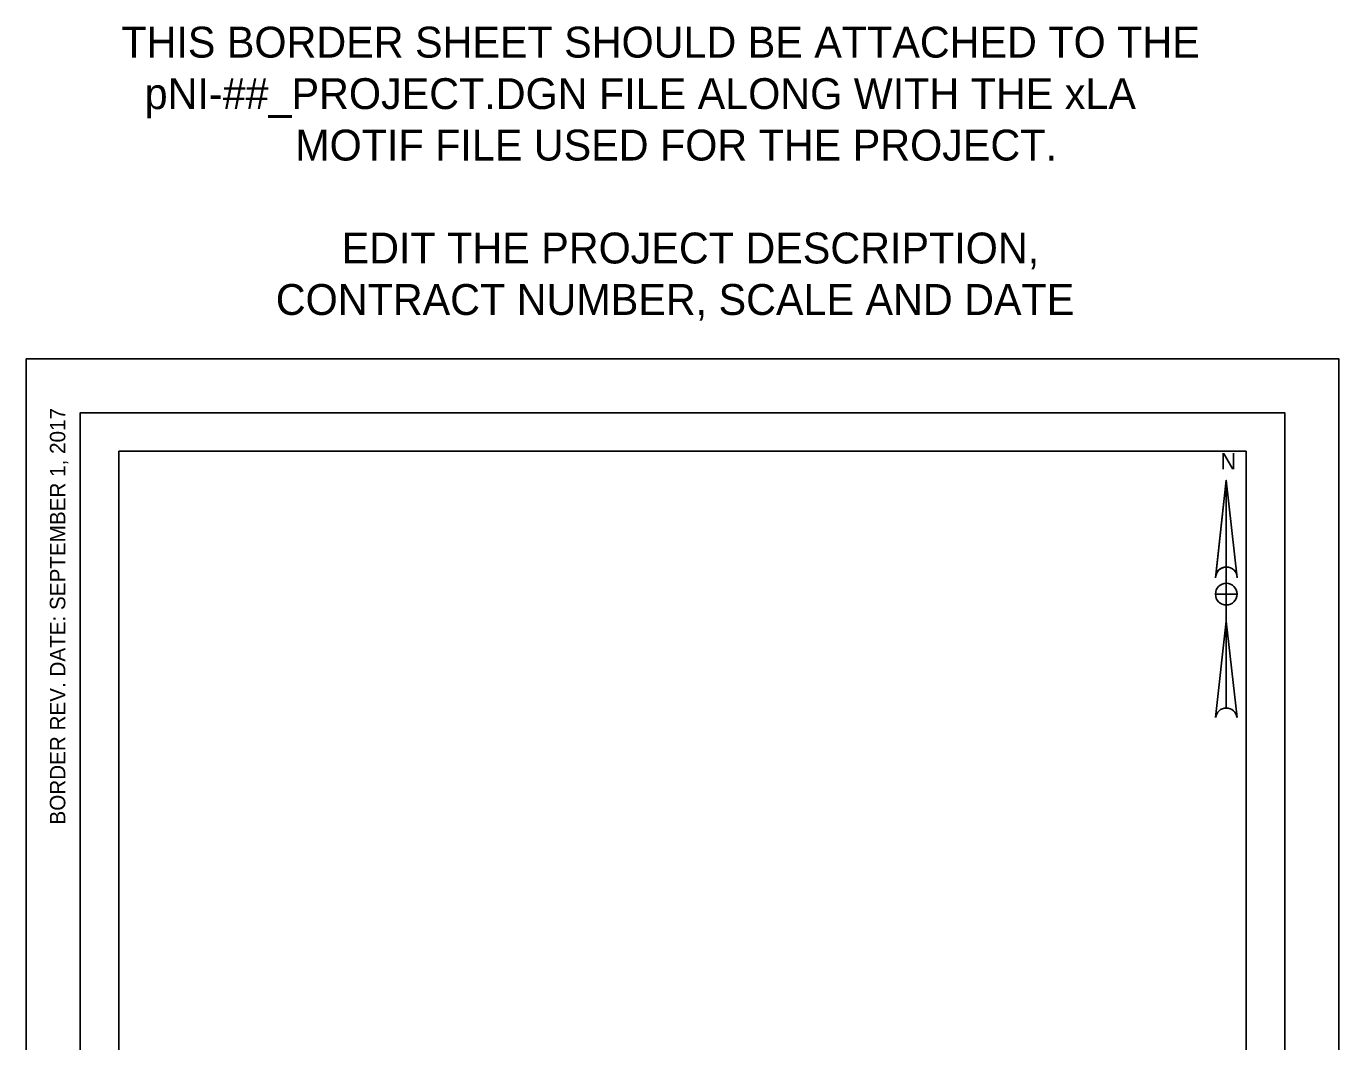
# Model space of a CAD drawing. Extents: x 0 to 8.5, y 0 to 13.2.
# Drawn here: x 0 to 8.5, y 6.58 to 13.15 of the extents above; entities that cross this region are included whole.
import ezdxf

# ---------------------------------------------------------------- set-up
doc = ezdxf.new("R2010")
doc.units = 0
for name, color, linetype in [('G-ANNO-SYMB', 7, 'Continuous'), ('G-BORD-LINE', 7, 'Continuous'), ('G-USER-CLIP', 7, 'Continuous'), ('G-USER-PAGE', 7, 'Continuous'), ('G-USER-TEXT', 7, 'Continuous')]:
    doc.layers.add(name, color=color, linetype=linetype)

msp = doc.modelspace()

# ---------------------------------------------------------------- linework, layer by layer
at = {"layer": 'G-ANNO-SYMB'}
for p, q in [((7.7016, 9.5803), (7.7718, 10.213)), ((7.7718, 8.7376), (7.7718, 10.213)), ((7.8421, 9.5803), (7.7718, 10.213)), ((7.7718, 9.4753), (7.7718, 9.5455)), ((7.7016, 9.4753), (7.7718, 9.4753)), ((7.7016, 9.4753), (7.7016, 9.4753)), ((7.7016, 9.4753), (7.7016, 9.4753)), ((7.8421, 9.4753), (7.7718, 9.4753)), ((7.7718, 9.4753), (7.7718, 9.405)), ((7.8421, 9.4753), (7.8421, 9.4753)), ((7.8421, 9.4753), (7.8421, 9.4753)), ((7.7025, 8.6755), (7.7718, 9.2993)), ((7.8412, 8.6755), (7.7718, 9.2993))]:
    msp.add_line(p, q, dxfattribs=at)
for points in [[(7.7718, 9.6505), (7.7718, 9.6505), (7.7718, 10.213), (7.7034, 9.5956)], [(7.7718, 9.5455), (7.7718, 9.4753), (7.8421, 9.4753)], [(7.7718, 9.405), (7.7718, 9.4753), (7.7016, 9.4753), (7.7016, 9.4753)], [(7.7718, 9.405), (7.7718, 9.405)], [(7.8412, 8.6755), (7.7718, 9.2993), (7.7718, 8.7376)]]:
    msp.add_lwpolyline(points, dxfattribs=at)
for centre, radius, start, end in [((7.772, 9.5802), 0.0703, 90, 180), ((7.772, 9.5802), 0.0703, 90.09047, 167.34843), ((7.772, 9.5802), 0.0703, 0, 90), ((7.7718, 9.4753), 0.0703, 90, 180), ((7.7718, 9.4753), 0.0703, 0, 90), ((7.7718, 9.4753), 0.0703, 0.00121, 89.99879), ((7.7718, 9.4753), 0.0703, 180, 270), ((7.7718, 9.4753), 0.0703, 180, 270), ((7.7718, 9.4753), 0.0703, 270, 360), ((7.7718, 8.6678), 0.0698, 6.34387, 173.65613), ((7.7718, 8.6678), 0.0698, 6.34387, 90)]:
    msp.add_arc(centre, radius, start, end, dxfattribs=at)
at = {"layer": 'G-BORD-LINE'}
msp.add_lwpolyline([(0.35, 0.8607), (0.35, 0.35), (8.15, 0.35), (8.15, 10.65), (0.35, 10.65), (0.35, 0.8607)], dxfattribs=at)
at = {"layer": 'G-USER-CLIP'}
msp.add_lwpolyline([(0.6, 10.4), (7.9, 10.4), (7.9, 2.35), (0.6, 2.35)], close=True, dxfattribs=at)
at = {"layer": 'G-USER-PAGE'}
msp.add_lwpolyline([(0, 11), (8.5, 11), (8.5, 0), (0, 0)], close=True, dxfattribs=at)

# ---------------------------------------------------------------- texts
at = {"layer": 'G-ANNO-SYMB'}
msp.add_text('N', height=0.105, dxfattribs=at).set_placement((7.7338, 10.2832))
at = {"layer": 'G-USER-TEXT'}
for s, p in [('THIS BORDER SHEET SHOULD BE ATTACHED TO THE', (0.6158, 12.9498)), ('pNI-##_PROJECT.DGN FILE ALONG WITH THE xLA ', (0.7667, 12.6165)), ('MOTIF FILE USED FOR THE PROJECT.', (1.7418, 12.2833)), ('EDIT THE PROJECT DESCRIPTION, ', (2.0425, 11.6166)), ('CONTRACT NUMBER, SCALE AND DATE', (1.6162, 11.2833))]:
    msp.add_text(s, height=0.2, dxfattribs=at).set_placement(p)
msp.add_text('BORDER REV. DATE: SEPTEMBER 1, 2017', height=0.1, rotation=90, dxfattribs=at).set_placement((0.253, 7.983))

doc.saveas('drawing.dxf')
